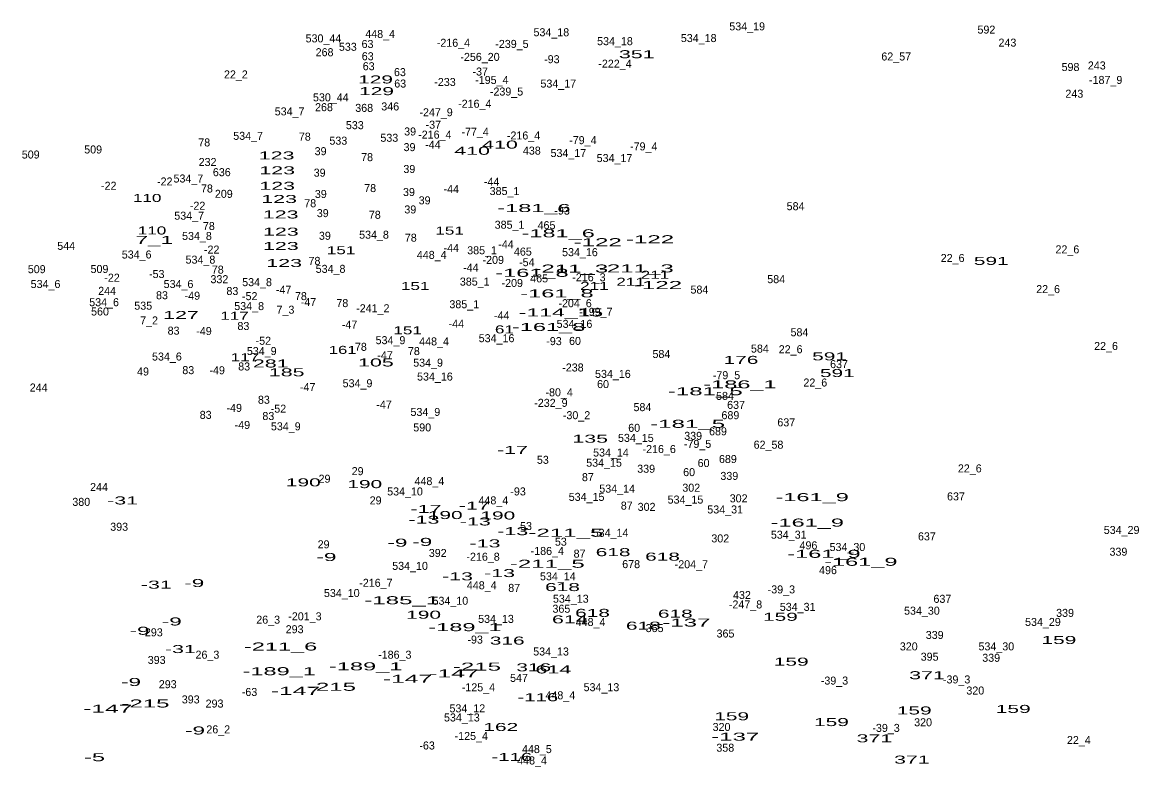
# Model space of a CAD drawing. Extents: x -661742 to -657295, y -1002932 to -996888.
# Drawn here: x -659871 to -659315, y -999837 to -999465 of the extents above; entities that cross this region are included whole.
import ezdxf
from ezdxf.enums import TextEntityAlignment as Align

# ---------------------------------------------------------------- set-up
doc = ezdxf.new("R2010")
doc.units = 0
doc.header["$LTSCALE"] = 1.6
doc.layers.add('24', color=7, linetype='Continuous')

msp = doc.modelspace()

# ---------------------------------------------------------------- texts
at = {"layer": '24'}
for s, p in [('534_18', (-659606.163, -999472.04)), ('534_19', (-659508.258, -999469.09)), ('592', (-659388.643, -999470.72)), ('530_44', (-659720.108, -999475.11)), ('63', (-659698.073, -999477.9)), ('448_4', (-659691.758, -999472.9)), ('-216_4', (-659655.116, -999477.31)), ('-239_5', (-659625.858, -999477.87)), ('534_18', (-659574.363, -999476.5)), ('534_18', (-659532.493, -999474.95)), ('243', (-659378.131, -999477.22)), ('268', (-659719.553, -999482.02)), ('533', (-659707.917, -999479.3)), ('63', (-659697.983, -999484.04)), ('63', (-659697.493, -999489.02)), ('-256_20', (-659641.831, -999484.36)), ('-93', (-659605.91, -999485.52)), ('-222_4', (-659574.347, -999487.76)), ('62_57', (-659433.736, -999484.15)), ('598', (-659346.593, -999489.42)), ('243', (-659333.461, -999488.64)), ('22_2', (-659763.895, -999493.11)), ('63', (-659681.873, -999491.97)), ('-37', (-659641.721, -999491.68)), ('63', (-659681.733, -999497.68)), ('-233', (-659659.335, -999496.9)), ('-195_4', (-659635.916, -999495.88)), ('534_17', (-659602.688, -999497.69)), ('-187_9', (-659329.007, -999495.88)), ('530_44', (-659716.418, -999504.57)), ('-239_5', (-659628.568, -999501.67)), ('243', (-659344.671, -999502.76)), ('534_7', (-659737.035, -999511.6)), ('268', (-659719.843, -999509.49)), ('368', (-659699.743, -999509.84)), ('346', (-659686.727, -999509.12)), ('-216_4', (-659644.456, -999507.77)), ('-247_9', (-659663.798, -999512.03)), ('533', (-659704.437, -999518.48)), ('39', (-659676.783, -999521.62)), ('-37', (-659665.181, -999518.25)), ('-77_4', (-659644.278, -999521.81)), ('78', (-659779.723, -999527.11)), ('534_7', (-659757.775, -999523.82)), ('78', (-659729.433, -999524.2)), ('533', (-659712.667, -999526.23)), ('533', (-659687.177, -999524.78)), ('-216_4', (-659664.426, -999523.2)), ('-44', (-659665.393, -999528.2)), ('-216_4', (-659620.066, -999523.64)), ('-79_4', (-659590.398, -999525.97)), ('509', (-659866.477, -999533.15)), ('509', (-659835.267, -999530.62)), ('39', (-659721.533, -999531.48)), ('39', (-659677.073, -999529.45)), ('438', (-659615.921, -999531.19)), ('534_17', (-659597.648, -999532.4)), ('-79_4', (-659559.968, -999529.08)), ('232', (-659778.047, -999536.89)), ('78', (-659698.303, -999534.46)), ('534_17', (-659574.578, -999534.92)), ('636', (-659770.938, -999541.98)), ('39', (-659722.013, -999542.22)), ('39', (-659677.173, -999540.38)), ('-22', (-659827.455, -999548.76)), ('-22', (-659799.445, -999546.62)), ('534_7', (-659787.635, -999545.14)), ('78', (-659778.363, -999550.13)), ('78', (-659696.753, -999549.93)), ('-44', (-659656.183, -999550.38)), ('-44', (-659636.023, -999546.72)), ('209', (-659769.927, -999552.79)), ('39', (-659721.433, -999552.87)), ('39', (-659677.363, -999551.89)), ('39', (-659669.533, -999556.05)), ('385_1', (-659629.579, -999551.41)), ('-22', (-659783.055, -999558.75)), ('78', (-659726.733, -999557.48)), ('39', (-659676.683, -999560.6)), ('-93', (-659600.81, -999561.17)), ('584', (-659484.051, -999558.98)), ('534_7', (-659787.245, -999563.72)), ('39', (-659720.463, -999562.44)), ('78', (-659694.433, -999563.28)), ('78', (-659777.403, -999568.89)), ('385_1', (-659627.069, -999568.24)), ('465', (-659608.587, -999568.48)), ('534_8', (-659783.36, -999573.85)), ('39', (-659719.403, -999573.76)), ('534_8', (-659694.84, -999573.23)), ('78', (-659676.443, -999574.7)), ('-44', (-659628.843, -999578.01)), ('544', (-659848.726, -999578.81)), ('534_6', (-659813.504, -999583.12)), ('-22', (-659775.985, -999580.66)), ('448_4', (-659665.978, -999583.31)), ('-44', (-659656.183, -999579.83)), ('385_1', (-659640.799, -999581.01)), ('465', (-659620.417, -999581.67)), ('534_16', (-659591.878, -999581.95)), ('22_6', (-659348.14, -999580.56)), ('534_8', (-659781.61, -999585.68)), ('78', (-659724.603, -999586.31)), ('-209', (-659635.214, -999585.82)), ('-54', (-659618.419, -999586.97)), ('22_6', (-659405.53, -999584.85)), ('509', (-659863.467, -999590.45)), ('509', (-659832.097, -999590.36)), ('-22', (-659825.805, -999594.72)), ('-53', (-659803.445, -999592.87)), ('78', (-659772.953, -999590.66)), ('534_8', (-659716.55, -999590.29)), ('-44', (-659646.393, -999589.63)), ('-216_3', (-659587.372, -999594.5)), ('534_6', (-659859.064, -999597.86)), ('534_6', (-659792.564, -999597.86)), ('332', (-659772.137, -999595.46)), ('534_8', (-659753.31, -999596.93)), ('385_1', (-659644.469, -999596.66)), ('-209', (-659625.714, -999597.36)), ('465', (-659612.277, -999595.05)), ('584', (-659493.741, -999595.44)), ('22_6', (-659357.79, -999600.41)), ('244', (-659828.266, -999601.28)), ('83', (-659800.847, -999603.48)), ('-49', (-659785.655, -999603.73)), ('83', (-659765.647, -999601.35)), ('-52', (-659756.965, -999603.93)), ('-47', (-659740.015, -999600.7)), ('78', (-659731.373, -999603.91)), ('584', (-659532.131, -999600.65)), ('534_6', (-659829.784, -999606.97)), ('560', (-659831.827, -999611.6)), ('535', (-659810.227, -999608.7)), ('534_8', (-659757.26, -999608.9)), ('7_3', (-659739.101, -999610.71)), ('-47', (-659727.605, -999606.9)), ('78', (-659710.673, -999607.4)), ('-241_2', (-659695.42, -999609.99)), ('385_1', (-659649.699, -999607.97)), ('-204_6', (-659594.296, -999607.46)), ('7_2', (-659807.301, -999616.08)), ('-44', (-659630.973, -999613.58)), ('-199_7', (-659583.892, -999611.76)), ('83', (-659795.047, -999621.18)), ('-49', (-659779.835, -999621.38)), ('83', (-659760.137, -999618.86)), ('-47', (-659707.055, -999618.15)), ('-44', (-659653.663, -999617.75)), ('534_16', (-659594.588, -999617.78)), ('584', (-659482.111, -999621.99)), ('-52', (-659750.175, -999626.23)), ('534_9', (-659686.594, -999625.94)), ('448_4', (-659664.808, -999626.56)), ('534_16', (-659633.558, -999624.95)), ('-93', (-659604.84, -999626.41)), ('60', (-659594.337, -999626.31)), ('534_9', (-659750.964, -999631.37)), ('78', (-659701.393, -999629.26)), ('-47', (-659689.315, -999633.47)), ('78', (-659674.903, -999631.39)), ('584', (-659551.131, -999632.85)), ('584', (-659501.891, -999630.14)), ('22_6', (-659486.52, -999630.46)), ('22_6', (-659328.83, -999628.85)), ('534_6', (-659798.384, -999634.12)), ('83', (-659759.757, -999639.08)), ('534_9', (-659667.794, -999637.18)), ('637', (-659462.328, -999637.91)), ('49', (-659810.327, -999641.58)), ('83', (-659787.697, -999640.92)), ('-49', (-659773.245, -999640.97)), ('534_16', (-659664.378, -999644.12)), ('-238', (-659595.375, -999639.59)), ('534_16', (-659575.398, -999642.8)), ('-79_5', (-659518.604, -999643.43)), ('244', (-659862.496, -999649.6)), ('-47', (-659727.995, -999649.38)), ('534_9', (-659703.074, -999647.46)), ('60', (-659580.317, -999647.88)), ('22_6', (-659474.18, -999647.1)), ('83', (-659749.887, -999655.72)), ('-80_4', (-659602.261, -999651.99)), ('584', (-659519.331, -999653.79)), ('-49', (-659764.715, -999659.78)), ('-52', (-659742.615, -999660.17)), ('-47', (-659689.805, -999658.1)), ('-232_9', (-659606.388, -999657.26)), ('584', (-659560.631, -999659.41)), ('637', (-659513.808, -999658.28)), ('83', (-659778.997, -999663.26)), ('83', (-659747.667, -999663.84)), ('534_9', (-659669.154, -999661.81)), ('-30_2', (-659593.566, -999663.43)), ('689', (-659516.638, -999663.43)), ('637', (-659488.698, -999667)), ('-49', (-659760.645, -999668.31)), ('534_9', (-659738.944, -999668.99)), ('590', (-659670.727, -999669.53)), ('60', (-659564.747, -999669.75)), ('689', (-659522.848, -999671.48)), ('534_15', (-659563.913, -999674.77)), ('-79_5', (-659533.044, -999677.76)), ('339', (-659535.263, -999673.75)), ('62_58', (-659497.59, -999678.18)), ('534_14', (-659576.358, -999682.08)), ('-216_6', (-659552.247, -999680.35)), ('53', (-659610.417, -999685.73)), ('534_15', (-659579.813, -999687.18)), ('60', (-659530.037, -999687.34)), ('689', (-659517.898, -999685.34)), ('29', (-659703.023, -999691.4)), ('87', (-659587.903, -999694.39)), ('339', (-659558.763, -999690.2)), ('60', (-659537.287, -999691.88)), ('339', (-659517.183, -999693.78)), ('22_6', (-659396.95, -999690.02)), ('244', (-659832.326, -999699.32)), ('29', (-659719.573, -999695.18)), ('448_4', (-659667.138, -999696.37)), ('534_14', (-659573.258, -999700.12)), ('302', (-659536.211, -999699.67)), ('29', (-659694.033, -999706.01)), ('534_10', (-659679.327, -999701.54)), ('448_4', (-659635.148, -999706)), ('-93', (-659622.8, -999701.53)), ('534_15', (-659588.543, -999704.25)), ('534_15', (-659539.103, -999705.6)), ('302', (-659512.521, -999704.99)), ('637', (-659403.858, -999704.01)), ('380', (-659841.201, -999706.74)), ('87', (-659568.463, -999708.61)), ('302', (-659558.541, -999709.24)), ('534_31', (-659519.263, -999710.54)), ('393', (-659822.253, -999719.19)), ('53', (-659618.827, -999718.81)), ('534_14', (-659576.558, -999722.22)), ('534_29', (-659321.034, -999720.79)), ('29', (-659720.043, -999727.97)), ('53', (-659601.427, -999726.65)), ('302', (-659521.701, -999725.01)), ('534_31', (-659487.473, -999723.15)), ('637', (-659418.398, -999723.99)), ('392', (-659662.973, -999732.28)), ('-186_4', (-659608.186, -999731.27)), ('87', (-659592.053, -999732.61)), ('496', (-659477.613, -999728.48)), ('534_30', (-659458.124, -999729.32)), ('339', (-659322.623, -999731.66)), ('534_10', (-659676.807, -999738.73)), ('-216_8', (-659640.302, -999734.17)), ('678', (-659566.268, -999737.87)), ('-204_7', (-659536.166, -999737.93)), ('534_14', (-659602.918, -999743.95)), ('496', (-659467.843, -999740.87)), ('-216_7', (-659693.887, -999747.2)), ('448_4', (-659640.968, -999748.43)), ('87', (-659624.733, -999749.73)), ('534_10', (-659710.937, -999752.3)), ('534_13', (-659596.433, -999755.15)), ('432', (-659510.871, -999753.3)), ('-39_3', (-659491.158, -999750.5)), ('637', (-659410.648, -999755.21)), ('534_10', (-659656.647, -999756.18)), ('365', (-659601.143, -999760.16)), ('-247_8', (-659509.082, -999758.01)), ('534_31', (-659483.013, -999759.22)), ('534_30', (-659420.894, -999761.13)), ('26_3', (-659747.75, -999765.62)), ('-201_3', (-659729.38, -999763.95)), ('534_13', (-659633.843, -999765.24)), ('448_4', (-659586.548, -999766.8)), ('534_29', (-659360.384, -999766.76)), ('339', (-659349.313, -999762.23)), ('293', (-659804.923, -999771.95)), ('293', (-659734.523, -999770.4)), ('365', (-659554.533, -999769.83)), ('365', (-659519.093, -999772.54)), ('-93', (-659644.26, -999775.58)), ('339', (-659414.493, -999773.26)), ('26_3', (-659778.12, -999783.13)), ('-186_3', (-659684.442, -999783.13)), ('534_13', (-659606.313, -999781.53)), ('320', (-659427.461, -999778.98)), ('534_30', (-659383.674, -999778.97)), ('393', (-659803.493, -999785.75)), ('395', (-659417.033, -999784.13)), ('339', (-659386.253, -999784.67)), ('547', (-659622.337, -999794.73)), ('293', (-659797.963, -999797.87)), ('-125_4', (-659642.62, -999799.42)), ('534_13', (-659581.113, -999799.37)), ('-39_3', (-659464.598, -999796.06)), ('-39_3', (-659403.528, -999795.49)), ('393', (-659786.473, -999805.48)), ('-63', (-659757.08, -999801.75)), ('448_4', (-659601.668, -999803.41)), ('320', (-659394.191, -999801.03)), ('293', (-659774.563, -999807.55)), ('534_12', (-659648.173, -999809.93)), ('534_13', (-659650.903, -999814.5)), ('320', (-659420.301, -999816.9)), ('26_2', (-659772.71, -999820.45)), ('320', (-659521.061, -999819.24)), ('-39_3', (-659438.818, -999819.72)), ('-125_4', (-659646.2, -999823.76)), ('22_4', (-659342.42, -999825.77)), ('-63', (-659668.29, -999828.51)), ('448_5', (-659613.404, -999830.3)), ('358', (-659519.197, -999829.62)), ('448_4', (-659615.818, -999835.99))]:
    msp.add_text(s, height=4, dxfattribs=at).set_placement(p, align=Align.CENTER)
for s, width, p in [('351', 2, (-659563.447, -999483.02)), ('129', 1.95, (-659694.053, -999495.63)), ('129', 1.95, (-659693.563, -999501.48)), ('410', 2, (-659631.839, -999528.18)), ('123', 2, (-659743.527, -999533.6)), ('410', 2, (-659645.769, -999531.27)), ('123', 2, (-659743.237, -999541.05)), ('123', 2, (-659743.237, -999548.79)), ('110', 1.6, (-659808.26, -999554.86)), ('123', 2, (-659742.267, -999555.36)), ('-181_6', 2.2, (-659614.863, -999559.9)), ('123', 2, (-659741.497, -999563.1)), ('110', 1.6, (-659805.84, -999571.11)), ('123', 2, (-659741.397, -999571.7)), ('151', 1.6, (-659657.034, -999571.19)), ('-181_6', 2.2, (-659602.753, -999572.51)), ('7_1', 2.1, (-659804.673, -999575.84)), ('-122', 2.25, (-659582.981, -999576.96)), ('-122', 2.25, (-659556.811, -999575.5)), ('123', 2, (-659741.397, -999578.85)), ('151', 1.6, (-659711.284, -999580.96)), ('123', 2, (-659739.757, -999587.36)), ('591', 1.95, (-659386.213, -999586.32)), ('-161_8', 2.2, (-659615.843, -999592.27)), ('-211_3', 2.25, (-659596.447, -999590.15)), ('-211_3', 2.25, (-659563.687, -999590.06)), ('211', 1.6, (-659554.354, -999593.27)), ('151', 1.6, (-659674.244, -999598.85)), ('211', 1.6, (-659584.624, -999598.78)), ('211', 1.6, (-659566.534, -999596.75)), ('-122', 2.25, (-659552.831, -999598.38)), ('-161_8', 2.2, (-659603.343, -999602.55)), ('127', 2, (-659791.313, -999613.37)), ('117', 1.6, (-659764.589, -999613.74)), ('-114_15', 2.15, (-659601.349, -999612.09)), ('151', 1.6, (-659678.014, -999621.01)), ('61', 1.6, (-659629.613, -999620.55)), ('-161_8', 2.2, (-659607.513, -999619.33)), ('161', 1.55, (-659710.499, -999630.79)), ('117', 1.6, (-659759.359, -999634.44)), ('281', 2, (-659746.467, -999637.58)), ('105', 2, (-659693.884, -999637.07)), ('176', 1.95, (-659511.347, -999635.79)), ('591', 1.95, (-659467.063, -999634.02)), ('185', 2, (-659738.487, -999641.99)), ('591', 1.95, (-659463.183, -999642.36)), ('-186_1', 2.2, (-659511.843, -999648.01)), ('-181_5', 2.25, (-659529.197, -999651.45)), ('-181_5', 2.25, (-659538.017, -999667.74)), ('135', 2, (-659586.747, -999675.17)), ('-17', 2, (-659625.605, -999680.8)), ('190', 1.95, (-659730.179, -999697)), ('190', 1.95, (-659699.459, -999697.87)), ('-31', 2, (-659820.531, -999706.03)), ('-161_9', 2.2, (-659475.767, -999704.39)), ('-17', 2, (-659668.835, -999710.28)), ('-17', 2, (-659644.695, -999708.63)), ('-13', 2, (-659669.871, -999715.65)), ('190', 1.95, (-659659.229, -999713.34)), ('-13', 2, (-659644.171, -999716.53)), ('190', 1.95, (-659632.929, -999713.54)), ('-161_9', 2.2, (-659478.187, -999717.1)), ('-13', 2, (-659625.471, -999721.39)), ('-211_5', 2.25, (-659598.887, -999722.16)), ('-9', 2.1, (-659683.129, -999727.15)), ('-9', 2.1, (-659670.719, -999726.76)), ('-13', 2, (-659639.331, -999727.49)), ('618', 1.95, (-659575.283, -999731.88)), ('-161_9', 2.2, (-659469.857, -999732.71)), ('-9', 2.1, (-659718.609, -999734.32)), ('-211_5', 2.25, (-659608.197, -999737.67)), ('618', 1.95, (-659550.563, -999734.11)), ('-161_9', 2.2, (-659451.437, -999736.69)), ('-13', 2, (-659653.091, -999743.97)), ('-13', 2, (-659632.061, -999742.33)), ('-31', 2, (-659803.671, -999748.12)), ('-9', 2.1, (-659784.709, -999747.32)), ('618', 1.95, (-659600.583, -999749.33)), ('-185_1', 2.25, (-659680.947, -999755.91)), ('-9', 2.1, (-659795.959, -999766.52)), ('190', 1.95, (-659670.029, -999763.14)), ('614', 2, (-659596.918, -999765.47)), ('618', 1.95, (-659585.563, -999762.23)), ('618', 1.95, (-659544.173, -999762.62)), ('-137', 2.25, (-659538.655, -999767.07)), ('159', 1.95, (-659491.643, -999764.18)), ('-9', 2.1, (-659812.049, -999771.17)), ('-189_1', 2.2, (-659649.333, -999769.36)), ('618', 1.95, (-659560.163, -999768.63)), ('316', 1.95, (-659628.223, -999776.08)), ('159', 1.95, (-659352.393, -999775.79)), ('-31', 2, (-659791.651, -999780.31)), ('-211_6', 2.2, (-659741.533, -999779.04)), ('-189_1', 2.2, (-659698.993, -999788.95)), ('-215', 2.25, (-659643.361, -999789.09)), ('159', 1.95, (-659486.223, -999786.62)), ('-189_1', 2.2, (-659742.233, -999791.37)), ('-147', 2.3, (-659654.831, -999792.47)), ('316', 1.95, (-659614.983, -999789.43)), ('614', 2, (-659605.158, -999790.49)), ('371', 2, (-659418.343, -999793.38)), ('-9', 2.1, (-659816.319, -999796.77)), ('-215', 2.25, (-659715.871, -999799.17)), ('-147', 2.3, (-659678.091, -999795.18)), ('-147', 2.3, (-659734.121, -999801.19)), ('-116', 1.9, (-659612.921, -999804.38)), ('-147', 2.3, (-659827.951, -999810.11)), ('-215', 2.25, (-659809.121, -999807.51)), ('159', 1.95, (-659424.723, -999811)), ('159', 1.95, (-659375.213, -999810.23)), ('159', 1.95, (-659516.003, -999813.91)), ('159', 1.95, (-659466.113, -999816.8)), ('-9', 2.1, (-659784.329, -999821.01)), ('162', 1.95, (-659631.433, -999819.25)), ('-137', 2.25, (-659514.225, -999824.08)), ('371', 2, (-659444.653, -999824.92)), ('-5', 2.2, (-659834.544, -999834.37)), ('-116', 1.9, (-659625.911, -999834.24)), ('371', 2, (-659425.893, -999835.56))]:
    msp.add_text(s, height=4, dxfattribs=dict(at, width=width)).set_placement(p, align=Align.CENTER)

doc.saveas('drawing.dxf')
